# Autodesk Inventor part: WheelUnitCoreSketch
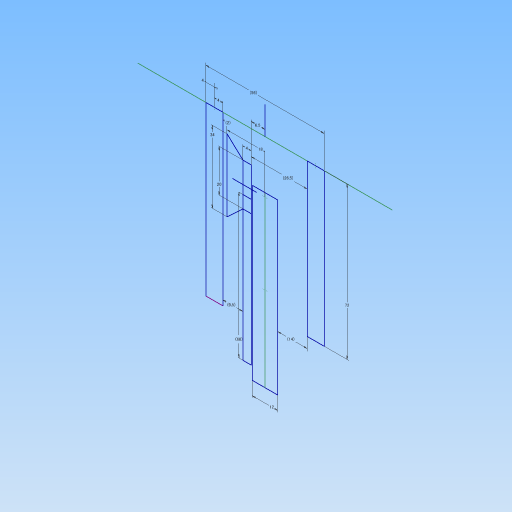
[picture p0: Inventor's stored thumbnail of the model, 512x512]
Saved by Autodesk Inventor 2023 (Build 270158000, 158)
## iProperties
Created: 2024-05
Part Number: WheelUnitCoreSketch
Material: 一般
Document SubType Name: Modeling
Designer: kumagai
Density: 1 g/cm^3
Appearance: 既定
Author: kumagai
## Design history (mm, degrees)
derived "SteerBase.ipt"
  sketch "スケッチ5"
    geometry: L1 (0, -60.2)-(0, 60.2) reference; L2 (-60.2, 0)-(60.2, 0) reference; L3 (-19, 34.059)-(-19, -34.059) reference; L4 (-28, 27.148)-(-28, -27.148) reference; L5 (-3, 38.884)-(-3, 34.135) reference; L6 (-3, 9.865)-(-3, -38.884) reference; L7 (3, 38.884)-(3, 34.135) reference; L8 (3, 9.865)-(3, -38.884) reference; L9 (28, 27.148)-(28, -27.148) reference; L10 (19, 34.059)-(19, -34.059) reference; L11 (-38.884, 3)-(38.884, 3) reference; L12 (-38.884, -3)-(38.884, -3) reference; C1 r 11 at (0, 22) reference; C2 r 10 at (0, 22) reference; C3 r 4.9 at (0, 22) reference; C4 r 4 at (0, 22) reference; C5 r 1.65 at (-15, 10) reference; C6 r 1.65 at (15, 10) reference; C7 r 1.65 at (0, -18) reference; C8 r 11 at (-18.508, -11.894) reference; C9 r 11 at (18.508, -11.894) reference; C10 r 1.65 at (-18.508, -11.894) reference; C11 r 1.65 at (18.508, -11.894) reference; C12 r 5.5 at (-18.508, -11.894) reference; C13 r 5.5 at (0, -18) reference; C14 r 5.5 at (18.508, -11.894) reference; C15 r 5.5 at (-15, 10) reference; C16 r 5.5 at (15, 10) reference; C17 r 2.65 at (-15, 10) reference; C18 r 2.65 at (-18.508, -11.894) reference; C19 r 2.65 at (0, -18) reference; C20 r 2.65 at (18.508, -11.894) reference; C21 r 2.65 at (15, 10) reference; C22 r 43 at (0, 0) reference; C23 r 42 at (0, 0) reference; C24 r 6 at (0, 0) reference; C25 r 2 at (0, 0) reference; C26 r 3 at (0, 0) reference; C27 r 1.65 at (24, 17) reference; C28 r 1.65 at (-24, 17) reference; C29 r 1.65 at (24, -24) reference; C30 r 1.65 at (-24, -24) reference; C31 r 2.65 at (24, -24) reference; C32 r 2.65 at (24, 17) reference; C33 r 2.65 at (-24, -24) reference; C34 r 2.65 at (-24, 17) reference; A1 r 12.5 centre (0, 22) between (-3, 34.135) and (-3, 9.865) reference; 2 further points
    constraints: 1 other
sketch "BaseSketch"
  geometry: L1 (0, -60.2)-(0, 60.2) reference; L2 (-60.2, 0)-(60.2, 0) reference; L3 (19, 34.059)-(19, -34.059) reference; L4 (28, 27.148)-(28, -27.148) reference; L5 (-19, 34.059)-(-19, -34.059) reference; L6 (-28, 27.148)-(-28, -27.148) reference; C1 r 43 at (0, 0) reference; 7 further points
  constraints: 1 other
sketch "Side"
  geometry: L1 (-85.136, 0)-(85.136, 0) reference; L2 (0, 60.2)-(0, -60.2) reference; L3 (0, 22)-(-24.895, 22); C1 r 10 at (-24.895, 22); C2 r 34 at (-63, 0); C3 r 40 at (-63, 0); C4 r 2 at (-24.895, 22); C5 r 17 at (-24.895, 22); 2 further points
  constraints: 5 centre point, 5 coincident, 2 end point, 1 horizontal, 1 point on line, 1 tangent
  dimensions: "d2" = 20 diameter of C1; "d3" = 80 diameter of C3; "d4" = 68 diameter of C2; "d5" = 4 diameter of C4; "d14" = 2 dimension on C4 C3 (derived); "d16" = 63 distance from line of L2 C2.centre; "d17" = 24.89488 distance from line of L2 L3.end (derived); "d18" = 34 diameter of C5
sketch "Front"
  geometry: L1 (0, -97)-(0, -29) reference; L2 (0, -103)-(0, -23) reference; L3 (-60.2, 0)-(60.2, 0) reference; L4 (-28, 0)-(-20, 0); L5 (-20, 0)-(-20, -79.404); L6 (-20, -79.404)-(-28, -79.404); L7 (-28, -79.404)-(-28, 0); L8 (20, 0)-(28, 0); L9 (28, 0)-(28, -72); L10 (28, -72)-(20, -72); L11 (20, -72)-(20, 0); L12 (0, 0)-(0, 13.248); L13 (-6, -23)-(6, -23); L14 (6, -23)-(6, -103); L15 (6, -103)-(-6, -103); L16 (-6, -103)-(-6, -23); L17 (-6.5, -29)-(-10.5, -29); L18 (-10.5, -29)-(-10.5, -97); L19 (-10.5, -97)-(-6.5, -97); L20 (-6.5, -97)-(-6.5, -29); L21 (-10.5, -34.895)-(-6.5, -34.895); L22 (-6.5, -34.895)-(-6.5, -14.895); L23 (-6.5, -14.895)-(-10.5, -14.895); L24 (-10.5, -14.895)-(-10.5, -34.895); L25 (-15.456, -24.895)-(-4.042, -24.895); L26 (-18, -7.895)-(-18, -41.895); L27 (-18, -7.895)-(-10.5, -14.895); L28 (-10.5, -34.895)-(-18, -41.895); 4 further points
  constraints: 50 end point, 5 horizontal, 5 point on line, 4 collinear, 4 vertical, 2 midpoint, 5 other
  dimensions: "d7" = 4 distance from line of L5 point (-24, 0); "d8" = 4 distance from line of point (-24, 0) L7; "d9" = 12 distance between parallel lines of L14 L16; "d10" = 6.5 distance between parallel lines of L12 L22; "d11" = 4 distance between parallel lines of L22 L24; "d12" = 20 distance between parallel lines of L21 L23; "d13" = 68 distance between parallel lines of L19 L17 (derived); "d15" = 72 distance between parallel lines of L10 L3; "d19" = 56 distance between parallel lines of L7 L9 (derived); "d20" = 14 distance between parallel lines of L14 L11 (derived); "d21" = 9.5 distance between parallel lines of L5 L18 (derived); "d22" = 34 distance of L26.start L26.end; "d23" = 18 distance from line of point (0, -24.895) L26; "d24" = 2 distance between parallel lines of L5 L26 (derived); "d25" = 26.5 distance between parallel lines of L11 L22 (derived)
feature "ソリッド1::SteerBase.ipt" dims "d0" = 10
tag "TaggingFeature1"
node "ソリッド1"
